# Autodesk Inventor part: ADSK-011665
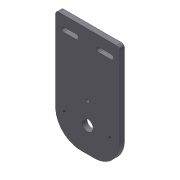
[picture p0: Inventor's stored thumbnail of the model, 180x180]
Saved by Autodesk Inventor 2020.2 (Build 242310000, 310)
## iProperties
Created: 2000-02
Part Number: ADSK-011665
Material: Pearson HRS
Description: PLT-24,XX,FH,03,085,050,BEARING MOUNT
Document SubType Name: Modeling
Designer: sspink
Density: 7.83 g/cm^3
Appearance: Métal - Acier
Mass: 1979.29 g
Surface Area: 598.301 cm^2
Volume: 252.783 cm^3
Control State: 0
Master: False
Checked Out: False
Shininess: 0.0
Length Units: 11269
Angle Units: 11279
Time Units: 11290
Mass Units: 11283
Length Display Precision: 3
Angle Display Precision: 2
Compacted: True
Cutlength: 8.50
Material Desc: FLAT,HRS,0.375X05.000
Material_Number: A084412
Dimensions: 216x10x127 mm
Mass: 1,979 kg
VLT_Material: Pearson HRS
Density: 0.0
Volumn: 0.0
Area: 0.0
PropertySet Name: Model Information
Author: sspink
Revision Number: -
Title: PLT-24,XX,FH,03,085,050,BEARING MOUNT
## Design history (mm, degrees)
node "Solide1"
  node "Extrusion1" dims "d2" = 10, "d3" = 0
  node "Hole1" dims "d5" = 22, "d6" = 9.525, "d7" = 6.35, "d8" = 60 deg, "d9" = 19.05, "d10" = 118 deg, "d44" = 6
  node "Fillet1" dims "d11" = 50
  node "Extrusion2" dims "d17" = 9.525, "d18" = 0
  node "Fillet2" dims "d19" = 6
  node "Hole2" dims "d22" = 7, "d23" = 9.525, "d24" = 6.35, "d25" = 60 deg, "d26" = 19.05, "d27" = 118 deg, "d41" = 6
  node "Hole3" dims "d32" = 6.647, "d33" = 9.525, "d34" = 6.35, "d35" = 60 deg, "d36" = 22.2, "d37" = 118 deg, "d43" = 16
sketch "Sketch1"
  geometry: L1 (-63.5, -108)-(63.5, -108); L2 (63.5, -108)-(63.5, 108); L3 (63.5, 108)-(-63.5, 108); L4 (-63.5, 108)-(-63.5, -108); 3 further points
  constraints: 8 end point, 2 midpoint, 2 parallel, 1 horizontal, 1 horizontal alignment, 1 perpendicular, 1 vertical alignment
  dimensions: "d0" = 127 distance between parallel lines of L2 L4; "d1" = 216 distance between parallel lines of L1 L3
sketch "Sketch2"
  geometry: L1 (63.5, -108)-(-63.5, -108) reference; L2 (-63.5, 108)-(63.5, 108) reference; L3 (0, 108)-(0, -108); 1 further point
  constraints: 2 end point, 2 midpoint, 1 point on line
  dimensions: "d4" = 50 distance from line of point (0, -58) L1
sketch "Sketch3"
  geometry: L1 (-63.5, 108)-(63.5, 108) reference; L2 (-47.5, 87.5)-(-22.5, 87.5); L3 (-22.5, 87.5)-(-22.5, 78.5); L4 (-22.5, 78.5)-(-47.5, 78.5); L5 (-47.5, 78.5)-(-47.5, 87.5); L6 (22.5, 87.5)-(47.5, 87.5); L7 (47.5, 87.5)-(47.5, 78.5); L8 (47.5, 78.5)-(22.5, 78.5); L9 (22.5, 78.5)-(22.5, 87.5); L10 (-22.5, 83)-(22.5, 83); A1 r 4.5 centre (-47.5, 83) between (-47.5, 87.5) and (-47.5, 78.5); A2 r 4.5 centre (-22.5, 83) between (-22.5, 78.5) and (-22.5, 87.5); A3 r 4.5 centre (22.5, 83) between (22.5, 87.5) and (22.5, 78.5); A4 r 4.5 centre (47.5, 83) between (47.5, 78.5) and (47.5, 87.5); 2 further points
  constraints: 18 end point, 8 point on circle, 4 centre point, 4 parallel, 4 tangent, 3 horizontal, 2 midpoint, 2 perpendicular, 1 collinear, 1 equal radius, 1 horizontal alignment, 1 vertical alignment
  dimensions: "d12" = 25 distance between parallel lines of L3 L5; "d13" = 9 distance between parallel lines of L4 L2; "d15" = 25 distance from line of A1.centre L1; "d39" = 45 distance of L10.start L10.end
sketch "Sketch4"
  geometry: C1 r 11 at (0, -58) reference; 1 further point
  constraints: 1 vertical alignment
  dimensions: "d40" = 42 distance of C1.centre point (0, -16)
sketch "Sketch5"
  geometry: L1 (-57.5, 108)-(57.5, 108) reference; L2 (13.5, -108)-(-13.5, -108) reference; L3 (0, 108)-(0, -108); L4 (-45, -58)-(45, -58); C1 r 11 at (0, -58) reference; 1 further point
  constraints: 4 end point, 3 midpoint, 1 coincident, 1 horizontal, 1 point on line
  dimensions: "d42" = 90 distance of L4.start L4.end
node "Corps solides"
node "Corps surfaciques"
